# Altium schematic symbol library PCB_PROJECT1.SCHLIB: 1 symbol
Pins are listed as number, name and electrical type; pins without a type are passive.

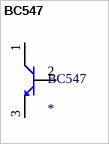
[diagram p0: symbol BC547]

## BC547
designator BC547
pins: 1, 2, 3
